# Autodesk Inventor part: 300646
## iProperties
Created: 2007-12
Part Number: 300646
Document SubType Name: Modeling
Designer: MM
Density: 7.85 g/cm^3
Mass: 265.832 g
Surface Area: 247.186 cm^2
Volume: 33.864 cm^3
Material: Steel
Description: LEFT SIDE SPRING BRACKET
Component Category: Back Component
Author: MM
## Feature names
1. TaggingFeature2
